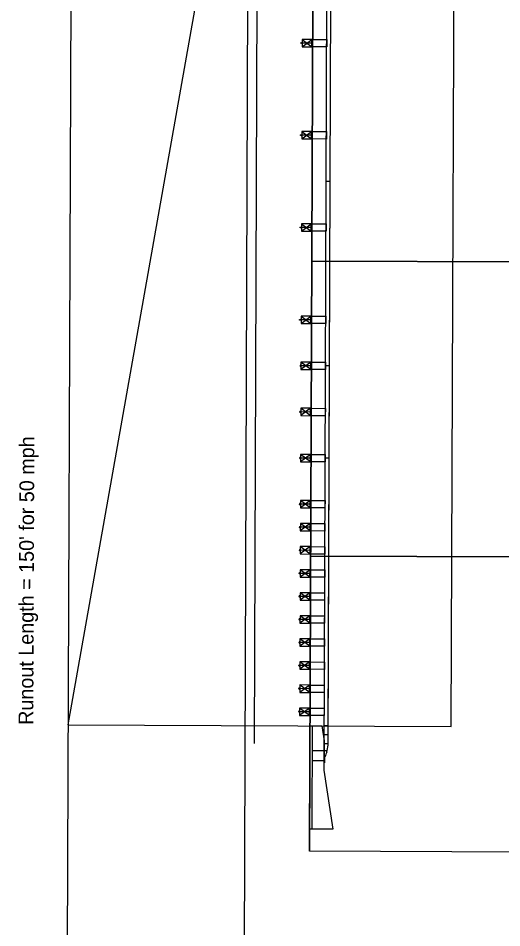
# Model space of a CAD drawing. Extents: x 15359458 to 15360238, y 8797399 to 8799222.
# Drawn here: x 15359892.3 to 15359925.1, y 8798363.3 to 8798425 of the extents above; entities that cross this region are included whole.
import ezdxf

# ---------------------------------------------------------------- set-up
doc = ezdxf.new("R2010")
doc.units = 0
for name, color, linetype in [('_CIVIL_CONSTRUCTION', 7, 'Continuous'), ('Alignment', 7, 'Continuous'), ('MeshTop', 7, 'Continuous'), ('PhoTerrainVoid', 7, 'Continuous')]:
    doc.layers.add(name, color=color, linetype=linetype)

msp = doc.modelspace()

# ---------------------------------------------------------------- linework, layer by layer
at = {"layer": '_CIVIL_CONSTRUCTION'}
for p, q in [((15359913.233, 8798413.912), (15359913.281, 8798426.412)), ((15359913.504, 8798413.911), (15359913.551, 8798426.411)), ((15359911.504, 8798423.294), (15359911.497, 8798423.294)), ((15359911.6, 8798423.044), (15359912.269, 8798423.541)), ((15359912.268, 8798423.291), (15359911.601, 8798423.294)), ((15359911.602, 8798423.544), (15359912.267, 8798423.041)), ((15359912.267, 8798423.041), (15359912.269, 8798423.541)), ((15359912.269, 8798423.541), (15359913.27, 8798423.538)), ((15359913.27, 8798423.538), (15359913.268, 8798423.037)), ((15359913.268, 8798423.037), (15359912.267, 8798423.041)), ((15359911.577, 8798416.794), (15359912.245, 8798417.291)), ((15359911.579, 8798417.294), (15359912.243, 8798416.791)), ((15359912.243, 8798416.791), (15359912.245, 8798417.291)), ((15359912.245, 8798417.291), (15359913.246, 8798417.288)), ((15359913.246, 8798417.288), (15359913.244, 8798416.787)), ((15359911.481, 8798417.044), (15359911.474, 8798417.044)), ((15359912.244, 8798417.041), (15359911.578, 8798417.044)), ((15359913.244, 8798416.787), (15359912.243, 8798416.791)), ((15359913.084, 8798374.517), (15359913.233, 8798413.912)), ((15359913.504, 8798413.911), (15359913.233, 8798413.912)), ((15359913.504, 8798413.911), (15359913.233, 8798413.912)), ((15359913.36, 8798375.711), (15359913.504, 8798413.911)), ((15359911.553, 8798410.544), (15359912.222, 8798411.041)), ((15359911.555, 8798411.044), (15359912.22, 8798410.541)), ((15359912.22, 8798410.541), (15359912.222, 8798411.042)), ((15359912.222, 8798411.042), (15359913.223, 8798411.038)), ((15359913.223, 8798411.038), (15359913.221, 8798410.537)), ((15359911.457, 8798410.794), (15359911.45, 8798410.794)), ((15359912.221, 8798410.791), (15359911.554, 8798410.794)), ((15359913.221, 8798410.537), (15359912.22, 8798410.541)), ((15359911.53, 8798404.294), (15359912.198, 8798404.791)), ((15359911.531, 8798404.794), (15359912.196, 8798404.291)), ((15359912.196, 8798404.291), (15359912.198, 8798404.792)), ((15359912.198, 8798404.792), (15359913.199, 8798404.788)), ((15359913.199, 8798404.788), (15359913.197, 8798404.287)), ((15359911.433, 8798404.544), (15359911.426, 8798404.544)), ((15359912.197, 8798404.541), (15359911.53, 8798404.544)), ((15359913.197, 8798404.287), (15359912.196, 8798404.291)), ((15359911.466, 8798401.429), (15359911.437, 8798401.429)), ((15359911.437, 8798401.429), (15359911.437, 8798401.409)), ((15359911.466, 8798401.409), (15359911.437, 8798401.409)), ((15359911.504, 8798401.459), (15359911.466, 8798401.459)), ((15359911.466, 8798401.459), (15359911.466, 8798401.379)), ((15359911.504, 8798401.443), (15359911.466, 8798401.443)), ((15359911.503, 8798401.395), (15359911.466, 8798401.395)), ((15359911.503, 8798401.379), (15359911.466, 8798401.379)), ((15359911.504, 8798401.499), (15359911.503, 8798401.339)), ((15359911.52, 8798401.339), (15359911.503, 8798401.339)), ((15359911.52, 8798401.499), (15359911.504, 8798401.499)), ((15359911.521, 8798401.669), (15359911.519, 8798401.169)), ((15359912.188, 8798401.666), (15359911.519, 8798401.169)), ((15359912.187, 8798401.416), (15359911.52, 8798401.419)), ((15359912.186, 8798401.166), (15359911.521, 8798401.669)), ((15359912.186, 8798401.166), (15359912.188, 8798401.666)), ((15359913.185, 8798401.163), (15359912.186, 8798401.166)), ((15359912.188, 8798401.666), (15359913.187, 8798401.662)), ((15359913.187, 8798401.662), (15359913.185, 8798401.163)), ((15359913.457, 8798401.411), (15359913.186, 8798401.412)), ((15359913.36, 8798375.807), (15359913.457, 8798401.411)), ((15359911.454, 8798398.304), (15359911.425, 8798398.304)), ((15359911.425, 8798398.304), (15359911.425, 8798398.284)), ((15359911.454, 8798398.284), (15359911.425, 8798398.284)), ((15359911.492, 8798398.334), (15359911.454, 8798398.334)), ((15359911.454, 8798398.334), (15359911.454, 8798398.254)), ((15359911.492, 8798398.318), (15359911.454, 8798398.318)), ((15359911.492, 8798398.27), (15359911.454, 8798398.27)), ((15359911.492, 8798398.254), (15359911.454, 8798398.254)), ((15359911.492, 8798398.374), (15359911.491, 8798398.214)), ((15359911.508, 8798398.214), (15359911.491, 8798398.214)), ((15359911.509, 8798398.374), (15359911.492, 8798398.374)), ((15359911.509, 8798398.544), (15359911.507, 8798398.044)), ((15359912.176, 8798398.541), (15359911.507, 8798398.044)), ((15359912.175, 8798398.291), (15359911.508, 8798398.294)), ((15359912.174, 8798398.041), (15359911.509, 8798398.544)), ((15359912.174, 8798398.041), (15359912.176, 8798398.541)), ((15359913.173, 8798398.038), (15359912.174, 8798398.041)), ((15359912.176, 8798398.541), (15359913.175, 8798398.537)), ((15359913.175, 8798398.537), (15359913.173, 8798398.038)), ((15359911.443, 8798395.179), (15359911.413, 8798395.179)), ((15359911.413, 8798395.179), (15359911.413, 8798395.159)), ((15359911.442, 8798395.159), (15359911.413, 8798395.159)), ((15359911.443, 8798395.209), (15359911.442, 8798395.129)), ((15359911.48, 8798395.145), (15359911.442, 8798395.145)), ((15359911.48, 8798395.129), (15359911.442, 8798395.129)), ((15359911.48, 8798395.209), (15359911.443, 8798395.209)), ((15359911.48, 8798395.193), (15359911.443, 8798395.193)), ((15359911.497, 8798395.249), (15359911.48, 8798395.249)), ((15359911.48, 8798395.249), (15359911.48, 8798395.089)), ((15359911.496, 8798395.089), (15359911.48, 8798395.089)), ((15359911.497, 8798395.419), (15359911.495, 8798394.919)), ((15359912.164, 8798395.416), (15359911.495, 8798394.919)), ((15359912.163, 8798395.166), (15359911.496, 8798395.169)), ((15359912.162, 8798394.916), (15359911.497, 8798395.419)), ((15359912.162, 8798394.916), (15359912.164, 8798395.416)), ((15359913.162, 8798394.913), (15359912.162, 8798394.916)), ((15359912.164, 8798395.416), (15359913.163, 8798395.412)), ((15359913.163, 8798395.412), (15359913.162, 8798394.913)), ((15359913.433, 8798395.161), (15359913.163, 8798395.162)), ((15359911.431, 8798392.054), (15359911.401, 8798392.054)), ((15359911.401, 8798392.054), (15359911.401, 8798392.034)), ((15359911.431, 8798392.034), (15359911.401, 8798392.034)), ((15359911.468, 8798392.084), (15359911.431, 8798392.084)), ((15359911.431, 8798392.084), (15359911.431, 8798392.004)), ((15359911.468, 8798392.068), (15359911.431, 8798392.068)), ((15359911.468, 8798392.02), (15359911.431, 8798392.02)), ((15359911.468, 8798392.004), (15359911.431, 8798392.004)), ((15359911.485, 8798392.124), (15359911.468, 8798392.124)), ((15359911.468, 8798392.124), (15359911.468, 8798391.964)), ((15359911.484, 8798391.964), (15359911.468, 8798391.964)), ((15359911.486, 8798392.294), (15359911.484, 8798391.794)), ((15359912.152, 8798392.291), (15359911.484, 8798391.794)), ((15359912.151, 8798392.041), (15359911.485, 8798392.044)), ((15359912.15, 8798391.791), (15359911.486, 8798392.294)), ((15359912.15, 8798391.792), (15359912.152, 8798392.291)), ((15359912.152, 8798392.291), (15359913.152, 8798392.287)), ((15359913.152, 8798392.287), (15359913.15, 8798391.788)), ((15359913.15, 8798391.788), (15359912.15, 8798391.792)), ((15359911.48, 8798390.731), (15359911.478, 8798390.231)), ((15359912.146, 8798390.729), (15359911.478, 8798390.231)), ((15359912.144, 8798390.229), (15359911.48, 8798390.731)), ((15359912.144, 8798390.229), (15359912.146, 8798390.729)), ((15359912.146, 8798390.729), (15359913.146, 8798390.725)), ((15359913.146, 8798390.725), (15359913.144, 8798390.225)), ((15359911.425, 8798390.491), (15359911.395, 8798390.492)), ((15359911.395, 8798390.492), (15359911.395, 8798390.472)), ((15359911.425, 8798390.471), (15359911.395, 8798390.472)), ((15359911.462, 8798390.521), (15359911.425, 8798390.521)), ((15359911.425, 8798390.521), (15359911.425, 8798390.441)), ((15359911.462, 8798390.505), (15359911.425, 8798390.505)), ((15359911.462, 8798390.457), (15359911.425, 8798390.457)), ((15359911.462, 8798390.441), (15359911.425, 8798390.441)), ((15359911.479, 8798390.561), (15359911.462, 8798390.561)), ((15359911.462, 8798390.561), (15359911.462, 8798390.401)), ((15359911.478, 8798390.401), (15359911.462, 8798390.401)), ((15359912.145, 8798390.479), (15359911.479, 8798390.481)), ((15359913.144, 8798390.225), (15359912.144, 8798390.229)), ((15359911.419, 8798388.929), (15359911.389, 8798388.929)), ((15359911.389, 8798388.929), (15359911.389, 8798388.909)), ((15359911.419, 8798388.909), (15359911.389, 8798388.909)), ((15359911.456, 8798388.959), (15359911.419, 8798388.959)), ((15359911.419, 8798388.959), (15359911.419, 8798388.879)), ((15359911.456, 8798388.943), (15359911.419, 8798388.943)), ((15359911.456, 8798388.895), (15359911.419, 8798388.895)), ((15359911.456, 8798388.879), (15359911.419, 8798388.879)), ((15359911.457, 8798388.999), (15359911.456, 8798388.839)), ((15359911.472, 8798388.839), (15359911.456, 8798388.839)), ((15359911.473, 8798388.999), (15359911.457, 8798388.999)), ((15359911.474, 8798389.169), (15359911.472, 8798388.669)), ((15359912.14, 8798389.166), (15359911.472, 8798388.669)), ((15359912.139, 8798388.916), (15359911.473, 8798388.919)), ((15359912.138, 8798388.666), (15359911.474, 8798389.169)), ((15359912.138, 8798388.667), (15359912.14, 8798389.166)), ((15359912.138, 8798388.667), (15359912.14, 8798389.166)), ((15359912.14, 8798389.166), (15359913.14, 8798389.163)), ((15359912.14, 8798389.166), (15359913.14, 8798389.163)), ((15359913.14, 8798389.163), (15359913.138, 8798388.663)), ((15359913.14, 8798389.163), (15359913.138, 8798388.663)), ((15359913.138, 8798388.663), (15359912.138, 8798388.667)), ((15359913.138, 8798388.663), (15359912.138, 8798388.667)), ((15359911.468, 8798387.606), (15359911.466, 8798387.106)), ((15359912.134, 8798387.604), (15359911.466, 8798387.106)), ((15359912.133, 8798387.104), (15359911.468, 8798387.606)), ((15359912.133, 8798387.104), (15359912.134, 8798387.604)), ((15359912.134, 8798387.604), (15359913.134, 8798387.6)), ((15359913.134, 8798387.6), (15359913.132, 8798387.1)), ((15359911.384, 8798387.367), (15359911.383, 8798387.347)), ((15359911.413, 8798387.347), (15359911.383, 8798387.347)), ((15359911.413, 8798387.367), (15359911.384, 8798387.367)), ((15359911.451, 8798387.396), (15359911.413, 8798387.397)), ((15359911.413, 8798387.397), (15359911.413, 8798387.317)), ((15359911.45, 8798387.38), (15359911.413, 8798387.381)), ((15359911.45, 8798387.332), (15359911.413, 8798387.333)), ((15359911.45, 8798387.316), (15359911.413, 8798387.317)), ((15359911.451, 8798387.436), (15359911.45, 8798387.276)), ((15359911.467, 8798387.276), (15359911.45, 8798387.276)), ((15359911.467, 8798387.436), (15359911.451, 8798387.436)), ((15359912.134, 8798387.354), (15359911.467, 8798387.356)), ((15359913.132, 8798387.1), (15359912.133, 8798387.104)), ((15359911.407, 8798385.804), (15359911.378, 8798385.804)), ((15359911.378, 8798385.804), (15359911.378, 8798385.784)), ((15359911.407, 8798385.784), (15359911.378, 8798385.784)), ((15359911.445, 8798385.834), (15359911.407, 8798385.834)), ((15359911.407, 8798385.834), (15359911.407, 8798385.754)), ((15359911.445, 8798385.818), (15359911.407, 8798385.818)), ((15359911.444, 8798385.77), (15359911.407, 8798385.77)), ((15359911.444, 8798385.754), (15359911.407, 8798385.754)), ((15359911.445, 8798385.874), (15359911.444, 8798385.714)), ((15359911.461, 8798385.714), (15359911.444, 8798385.714)), ((15359911.461, 8798385.874), (15359911.445, 8798385.874)), ((15359911.462, 8798386.044), (15359911.46, 8798385.544)), ((15359912.129, 8798386.041), (15359911.46, 8798385.544)), ((15359912.128, 8798385.791), (15359911.461, 8798385.794)), ((15359912.127, 8798385.541), (15359911.462, 8798386.044)), ((15359912.127, 8798385.542), (15359912.129, 8798386.041)), ((15359912.129, 8798386.041), (15359913.128, 8798386.038)), ((15359913.128, 8798386.038), (15359913.126, 8798385.538)), ((15359913.126, 8798385.538), (15359912.127, 8798385.542)), ((15359911.456, 8798384.481), (15359911.454, 8798383.981)), ((15359912.123, 8798384.479), (15359911.454, 8798383.981)), ((15359912.121, 8798383.979), (15359911.456, 8798384.481)), ((15359912.121, 8798383.979), (15359912.123, 8798384.479)), ((15359912.123, 8798384.479), (15359913.122, 8798384.475)), ((15359913.122, 8798384.475), (15359913.12, 8798383.975)), ((15359911.401, 8798384.242), (15359911.372, 8798384.242)), ((15359911.372, 8798384.242), (15359911.372, 8798384.222)), ((15359911.401, 8798384.222), (15359911.372, 8798384.222)), ((15359911.439, 8798384.271), (15359911.401, 8798384.272)), ((15359911.401, 8798384.272), (15359911.401, 8798384.192)), ((15359911.439, 8798384.255), (15359911.401, 8798384.256)), ((15359911.438, 8798384.207), (15359911.401, 8798384.208)), ((15359911.438, 8798384.191), (15359911.401, 8798384.192)), ((15359911.439, 8798384.311), (15359911.438, 8798384.151)), ((15359911.455, 8798384.151), (15359911.438, 8798384.151)), ((15359911.455, 8798384.311), (15359911.439, 8798384.311)), ((15359912.122, 8798384.229), (15359911.455, 8798384.231)), ((15359913.12, 8798383.975), (15359912.121, 8798383.979)), ((15359911.395, 8798382.679), (15359911.366, 8798382.679)), ((15359911.366, 8798382.679), (15359911.366, 8798382.659)), ((15359911.395, 8798382.659), (15359911.366, 8798382.659)), ((15359911.433, 8798382.709), (15359911.395, 8798382.709)), ((15359911.395, 8798382.709), (15359911.395, 8798382.629)), ((15359911.433, 8798382.693), (15359911.395, 8798382.693)), ((15359911.433, 8798382.645), (15359911.395, 8798382.645)), ((15359911.432, 8798382.629), (15359911.395, 8798382.629)), ((15359911.433, 8798382.749), (15359911.432, 8798382.589)), ((15359911.449, 8798382.589), (15359911.432, 8798382.589)), ((15359911.449, 8798382.749), (15359911.433, 8798382.749)), ((15359911.45, 8798382.919), (15359911.448, 8798382.419)), ((15359912.117, 8798382.916), (15359911.448, 8798382.419)), ((15359912.116, 8798382.666), (15359911.449, 8798382.669)), ((15359912.115, 8798382.416), (15359911.45, 8798382.919)), ((15359912.115, 8798382.417), (15359912.117, 8798382.916)), ((15359912.117, 8798382.916), (15359913.116, 8798382.913)), ((15359913.116, 8798382.913), (15359913.114, 8798382.413)), ((15359913.114, 8798382.413), (15359912.115, 8798382.417)), ((15359911.444, 8798381.356), (15359911.442, 8798380.856)), ((15359912.109, 8798380.854), (15359911.444, 8798381.356)), ((15359911.389, 8798381.117), (15359911.36, 8798381.117)), ((15359911.36, 8798381.117), (15359911.36, 8798381.097)), ((15359911.389, 8798381.097), (15359911.36, 8798381.097)), ((15359911.427, 8798381.146), (15359911.389, 8798381.147)), ((15359911.389, 8798381.147), (15359911.389, 8798381.067)), ((15359911.427, 8798381.13), (15359911.389, 8798381.131)), ((15359911.427, 8798381.082), (15359911.389, 8798381.083)), ((15359911.427, 8798381.066), (15359911.389, 8798381.067)), ((15359911.427, 8798381.186), (15359911.426, 8798381.026)), ((15359911.443, 8798381.026), (15359911.426, 8798381.026)), ((15359911.444, 8798381.186), (15359911.427, 8798381.186)), ((15359912.111, 8798381.354), (15359911.442, 8798380.856)), ((15359912.11, 8798381.104), (15359911.443, 8798381.106)), ((15359912.109, 8798380.854), (15359912.111, 8798381.354)), ((15359913.108, 8798380.85), (15359912.109, 8798380.854)), ((15359912.111, 8798381.354), (15359913.11, 8798381.35)), ((15359913.11, 8798381.35), (15359913.108, 8798380.85)), ((15359911.383, 8798379.554), (15359911.354, 8798379.554)), ((15359911.354, 8798379.554), (15359911.354, 8798379.534)), ((15359911.383, 8798379.534), (15359911.354, 8798379.534)), ((15359911.384, 8798379.584), (15359911.383, 8798379.504)), ((15359911.421, 8798379.52), (15359911.383, 8798379.52)), ((15359911.421, 8798379.584), (15359911.384, 8798379.584)), ((15359911.421, 8798379.568), (15359911.384, 8798379.568)), ((15359911.438, 8798379.624), (15359911.421, 8798379.624)), ((15359911.421, 8798379.624), (15359911.421, 8798379.464)), ((15359911.438, 8798379.794), (15359911.436, 8798379.294)), ((15359912.105, 8798379.791), (15359911.436, 8798379.294)), ((15359912.104, 8798379.541), (15359911.437, 8798379.544)), ((15359912.103, 8798379.291), (15359911.438, 8798379.794)), ((15359912.103, 8798379.292), (15359912.105, 8798379.791)), ((15359912.105, 8798379.791), (15359913.104, 8798379.788)), ((15359913.104, 8798379.788), (15359913.103, 8798379.288)), ((15359911.421, 8798379.504), (15359911.383, 8798379.504)), ((15359911.437, 8798379.464), (15359911.421, 8798379.464)), ((15359913.103, 8798379.288), (15359912.103, 8798379.292)), ((15359911.378, 8798377.992), (15359911.348, 8798377.992)), ((15359911.348, 8798377.992), (15359911.348, 8798377.972)), ((15359911.377, 8798377.972), (15359911.348, 8798377.972)), ((15359911.378, 8798378.022), (15359911.377, 8798377.942)), ((15359911.415, 8798377.957), (15359911.377, 8798377.958)), ((15359911.415, 8798377.941), (15359911.377, 8798377.942)), ((15359911.415, 8798378.021), (15359911.378, 8798378.022)), ((15359911.415, 8798378.005), (15359911.378, 8798378.006)), ((15359911.432, 8798378.061), (15359911.415, 8798378.061)), ((15359911.415, 8798378.061), (15359911.415, 8798377.901)), ((15359911.431, 8798377.901), (15359911.415, 8798377.901)), ((15359911.432, 8798378.231), (15359911.431, 8798377.731)), ((15359912.099, 8798378.229), (15359911.431, 8798377.731)), ((15359912.098, 8798377.979), (15359911.431, 8798377.981)), ((15359912.097, 8798377.729), (15359911.432, 8798378.231)), ((15359912.097, 8798377.729), (15359912.099, 8798378.229)), ((15359913.097, 8798377.725), (15359912.097, 8798377.729)), ((15359912.099, 8798378.229), (15359913.098, 8798378.225)), ((15359913.098, 8798378.225), (15359913.097, 8798377.725)), ((15359912.109, 8798370.021), (15359912.136, 8798377.021)), ((15359912.136, 8798377.021), (15359912.927, 8798377.018)), ((15359912.276, 8798370.02), (15359912.302, 8798377.02)), ((15359912.927, 8798377.018), (15359913.09, 8798376.017)), ((15359913.365, 8798377.016), (15359913.094, 8798377.017)), ((15359913.09, 8798376.017), (15359913.083, 8798374.018)), ((15359913.36, 8798375.807), (15359913.089, 8798375.808)), ((15359913.362, 8798376.412), (15359913.092, 8798376.413)), ((15359912.296, 8798375.353), (15359913.298, 8798375.349)), ((15359913.265, 8798375.25), (15359913.209, 8798375.107)), ((15359912.294, 8798374.686), (15359913.112, 8798374.683)), ((15359913.111, 8798374.767), (15359913.11, 8798374.517)), ((15359913.083, 8798374.018), (15359913.692, 8798370.018)), ((15359913.084, 8798374.517), (15359913.11, 8798374.517)), ((15359913.692, 8798370.015), (15359912.109, 8798370.021)), ((15359913.692, 8798370.018), (15359913.692, 8798370.015))]:
    msp.add_line(p, q, dxfattribs=at)
for points in [[(15359911.558, 8798423.274), (15359911.504, 8798423.274), (15359911.504, 8798423.313), (15359911.558, 8798423.313)], [(15359911.601, 8798423.26), (15359911.558, 8798423.26), (15359911.558, 8798423.327), (15359911.602, 8798423.327)], [(15359911.535, 8798417.024), (15359911.48, 8798417.025), (15359911.481, 8798417.063), (15359911.535, 8798417.063)], [(15359911.578, 8798417.01), (15359911.535, 8798417.01), (15359911.535, 8798417.077), (15359911.578, 8798417.077)], [(15359911.511, 8798410.774), (15359911.457, 8798410.775), (15359911.457, 8798410.813), (15359911.511, 8798410.813)], [(15359911.554, 8798410.76), (15359911.511, 8798410.76), (15359911.511, 8798410.827), (15359911.554, 8798410.827)], [(15359911.487, 8798404.524), (15359911.433, 8798404.525), (15359911.433, 8798404.563), (15359911.488, 8798404.563)], [(15359911.53, 8798404.51), (15359911.487, 8798404.511), (15359911.488, 8798404.577), (15359911.531, 8798404.577)]]:
    msp.add_lwpolyline(points, dxfattribs=at)
for points in [[(15359912.267, 8798423.041), (15359912.269, 8798423.541), (15359911.602, 8798423.544), (15359911.6, 8798423.044)], [(15359912.243, 8798416.791), (15359912.245, 8798417.291), (15359911.579, 8798417.294), (15359911.577, 8798416.794)], [(15359912.22, 8798410.541), (15359912.222, 8798411.041), (15359911.555, 8798411.044), (15359911.553, 8798410.544)], [(15359912.196, 8798404.291), (15359912.198, 8798404.791), (15359911.531, 8798404.794), (15359911.53, 8798404.294)], [(15359912.186, 8798401.166), (15359912.188, 8798401.666), (15359911.521, 8798401.669), (15359911.519, 8798401.169)], [(15359912.174, 8798398.041), (15359912.176, 8798398.541), (15359911.509, 8798398.544), (15359911.507, 8798398.044)], [(15359912.162, 8798394.916), (15359912.164, 8798395.416), (15359911.497, 8798395.419), (15359911.495, 8798394.919)], [(15359912.15, 8798391.791), (15359912.152, 8798392.291), (15359911.486, 8798392.294), (15359911.484, 8798391.794)], [(15359912.144, 8798390.229), (15359912.146, 8798390.729), (15359911.48, 8798390.731), (15359911.478, 8798390.231)], [(15359912.138, 8798388.666), (15359912.14, 8798389.166), (15359911.474, 8798389.169), (15359911.472, 8798388.669)], [(15359912.133, 8798387.104), (15359912.134, 8798387.604), (15359911.468, 8798387.606), (15359911.466, 8798387.106)], [(15359912.127, 8798385.541), (15359912.129, 8798386.041), (15359911.462, 8798386.044), (15359911.46, 8798385.544)], [(15359912.121, 8798383.979), (15359912.123, 8798384.479), (15359911.456, 8798384.481), (15359911.454, 8798383.981)], [(15359912.115, 8798382.416), (15359912.117, 8798382.916), (15359911.45, 8798382.919), (15359911.448, 8798382.419)], [(15359912.109, 8798380.854), (15359912.111, 8798381.354), (15359911.444, 8798381.356), (15359911.442, 8798380.856)], [(15359912.103, 8798379.291), (15359912.105, 8798379.791), (15359911.438, 8798379.794), (15359911.436, 8798379.294)], [(15359912.097, 8798377.729), (15359912.099, 8798378.229), (15359911.432, 8798378.231), (15359911.431, 8798377.731)]]:
    msp.add_lwpolyline(points, close=True, dxfattribs=at)
for centre, major_axis, start_param, end_param in [((15359911.865, 8798375.796), (0.006, 1.542), 4.353641, 4.660842), ((15359914.433, 8798374.55), (-0.005, -1.379), 4.300427, 4.558114)]:
    msp.add_ellipse(centre, major_axis=major_axis, ratio=0.97085, start_param=start_param, end_param=end_param, dxfattribs=at)
at = {"layer": 'Alignment'}
for p, q in [((15359898.874, 8799211.577), (15359893.015, 8797661.588)), ((15359910.874, 8799211.531), (15359905.014, 8797661.542))]:
    msp.add_line(p, q, dxfattribs=at)
msp.add_lwpolyline([(15359921.719, 8798376.984), (15359922.286, 8798526.983), (15359895.719, 8798377.083)], close=True, dxfattribs=at)
at = {"layer": 'MeshTop'}
for p, q in [((15359908.36, 8798375.826), (15359908.578, 8798433.556)), ((15359913.362, 8798376.412), (15359913.579, 8798433.637))]:
    msp.add_line(p, q, dxfattribs=at)
at = {"layer": 'PhoTerrainVoid'}
for p, q in [((15359912.104, 8798368.521), (15359912.369, 8798438.52)), ((15359912.104, 8798368.521), (15359912.369, 8798438.52)), ((15359912.104, 8798368.521), (15359912.369, 8798438.52)), ((15359912.369, 8798438.52), (15359912.104, 8798368.521)), ((15359912.255, 8798408.52), (15359955.421, 8798408.357)), ((15359955.421, 8798408.357), (15359912.255, 8798408.52)), ((15359912.18, 8798388.52), (15359955.346, 8798388.357)), ((15359955.346, 8798388.357), (15359912.18, 8798388.52)), ((15359955.27, 8798368.357), (15359912.104, 8798368.521))]:
    msp.add_line(p, q, dxfattribs=at)

# ---------------------------------------------------------------- texts
at = {"layer": 'Alignment'}
msp.add_text("Runout Length = 150' for 50 mph", height=1, rotation=89.7834, dxfattribs=at).set_placement((15359893.364, 8798377.091))

doc.saveas('drawing.dxf')
